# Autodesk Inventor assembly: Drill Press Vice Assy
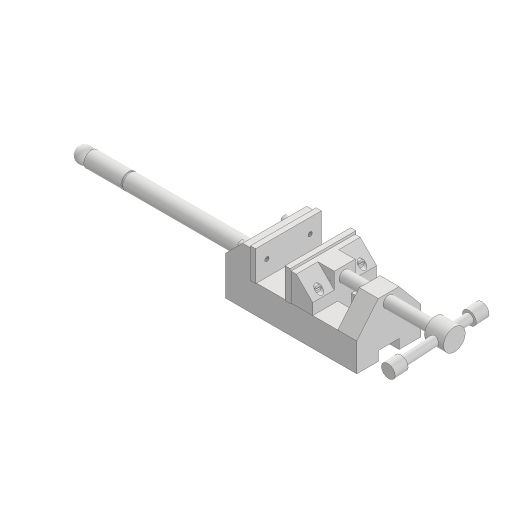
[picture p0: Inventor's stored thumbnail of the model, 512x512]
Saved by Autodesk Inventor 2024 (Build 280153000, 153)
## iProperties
Created: 2023-06
Part Number: Drill Press Vice Assy
Document SubType Name: Assembly
Designer: LENOVO-CADCIM
Author: LENOVO-CADCIM
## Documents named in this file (9)
- D:\PROJECTS\Project 2023\RESOURCES INVENTOR 2024\RESOURCES INVENTOR 2024\Inventor_2024_tut\Inventor_2024_tut\c13_Inv_2024_tut\c13_Inv_tut_2024\c13-tut02-inv\Drill Press vice\Drill Press Vice\Drill Press Vice Assy.iam
- D:\PROJECTS\Project 2023\RESOURCES INVENTOR 2024\RESOURCES INVENTOR 2024\Inventor_2024_tut\Inventor_2024_tut\c13_Inv_2024_tut\c13_Inv_tut_2024\c13-tut02-inv\Drill Press vice\Drill Press Vice\Base.ipt
- D:\PROJECTS\Project 2023\RESOURCES INVENTOR 2024\RESOURCES INVENTOR 2024\Inventor_2024_tut\Inventor_2024_tut\c13_Inv_2024_tut\c13_Inv_tut_2024\c13-tut02-inv\Drill Press vice\Drill Press Vice\Jaw Face.ipt
- D:\PROJECTS\Project 2023\RESOURCES INVENTOR 2024\RESOURCES INVENTOR 2024\Inventor_2024_tut\Inventor_2024_tut\c13_Inv_2024_tut\c13_Inv_tut_2024\c13-tut02-inv\Drill Press vice\Drill Press Vice\Movable Jaw.ipt
- D:\PROJECTS\Project 2023\RESOURCES INVENTOR 2024\RESOURCES INVENTOR 2024\Inventor_2024_tut\Inventor_2024_tut\c13_Inv_2024_tut\c13_Inv_tut_2024\c13-tut02-inv\Drill Press vice\Drill Press Vice\Cap Screw.ipt
- D:\PROJECTS\Project 2023\RESOURCES INVENTOR 2024\RESOURCES INVENTOR 2024\Inventor_2024_tut\Inventor_2024_tut\c13_Inv_2024_tut\c13_Inv_tut_2024\c13-tut02-inv\Drill Press vice\Drill Press Vice\Clamp Screw.ipt
- D:\PROJECTS\Project 2023\RESOURCES INVENTOR 2024\RESOURCES INVENTOR 2024\Inventor_2024_tut\Inventor_2024_tut\c13_Inv_2024_tut\c13_Inv_tut_2024\c13-tut02-inv\Drill Press vice\Drill Press Vice\Clamp Screw Handle.ipt
- D:\PROJECTS\Project 2023\RESOURCES INVENTOR 2024\RESOURCES INVENTOR 2024\Inventor_2024_tut\Inventor_2024_tut\c13_Inv_2024_tut\c13_Inv_tut_2024\c13-tut02-inv\Drill Press vice\Drill Press Vice\Handle Stop.ipt
- D:\PROJECTS\Project 2023\RESOURCES INVENTOR 2024\RESOURCES INVENTOR 2024\Inventor_2024_tut\Inventor_2024_tut\c13_Inv_2024_tut\c13_Inv_tut_2024\c13-tut02-inv\Drill Press vice\Drill Press Vice\Safety Handle.ipt
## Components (13 placed, 8 different names)
1. Base:1 — Mate:1, Mate:2, Mate:3, Mate:4, Mate:5, Insert:5, Insert:6, Mate:7, Insert:9
2. Jaw Face:1 — Insert:1, Insert:2
3. Jaw Face:2 — Mate:1, Mate:2, Mate:3, Mate:6
4. Movable Jaw:1
5. Cap Screw:1 — Insert:6
6. Cap Screw:2 — Insert:5
7. Cap Screw:3 — Insert:4
8. Cap Screw:4 — Insert:3
9. Clamp Screw:1 — Mate:7, Mate:8, Mate:10, Mate:11
10. Clamp Screw Handle:1 — Insert:7, Insert:8, Mate:11
11. Handle Stop:1 — Insert:8, Mate:10
12. Handle Stop:2 — Insert:7
13. Safety Handle:1 — Insert:9
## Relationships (19: Mate 10, Insert 9)
- Mate:1: Base:1 ↔ Jaw Face:2
- Mate:2: Base:1 ↔ Jaw Face:2
- Mate:3: Base:1 ↔ Jaw Face:2
- Mate:4: Base:1
- Mate:5: Base:1
- Mate:6: Jaw Face:2
- Insert:1: Jaw Face:1
- Insert:2: Jaw Face:1
- Insert:3: Cap Screw:4
- Insert:4: Cap Screw:3
- Insert:5: Base:1 ↔ Cap Screw:2
- Insert:6: Base:1 ↔ Cap Screw:1
- Mate:7: Base:1 ↔ Clamp Screw:1
- Mate:8: Clamp Screw:1
- Insert:7: Clamp Screw Handle:1 ↔ Handle Stop:2
- Insert:8: Clamp Screw Handle:1 ↔ Handle Stop:1
- Mate:10: Clamp Screw:1 ↔ Handle Stop:1
- Mate:11: Clamp Screw:1 ↔ Clamp Screw Handle:1
- Insert:9: Base:1 ↔ Safety Handle:1
